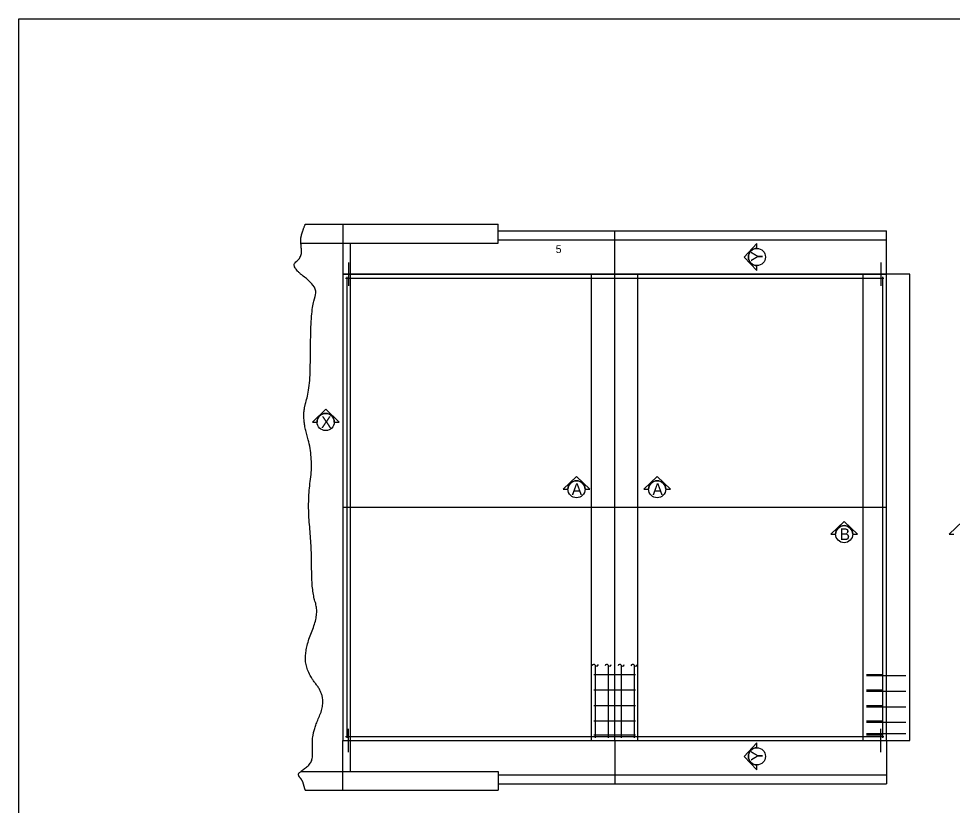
# Model space of a CAD drawing. Extents: x 1531 to 2925, y 1224 to 1658.
# Drawn here: x 2396.3 to 2456.4, y 1376.5 to 1427.1 of the extents above; entities that cross this region are included whole.
import ezdxf

# ---------------------------------------------------------------- set-up
doc = ezdxf.new("R2010")
doc.units = 0
for name, color, linetype in [('BD-EXIST-COSS', 7, 'Continuous'), ('BD-REMOVE', 7, 'Continuous'), ('D_BDR_TITLE_BLOCK_TEXT_TITLE', 7, 'Continuous'), ('R_Border_Scale', 7, 'Continuous'), ('R_Draft', 7, 'Continuous'), ('R_Survey Control', 7, 'Continuous'), ('R_Wall', 7, 'Continuous')]:
    doc.layers.add(name, color=color, linetype=linetype)

msp = doc.modelspace()

# ---------------------------------------------------------------- linework, layer by layer
at = {"layer": 'BD-EXIST-COSS'}
for p, q in [((2417.555, 1411.436), (2417.555, 1409.936)), ((2451.817, 1411.436), (2451.817, 1409.936)), ((2417.352, 1410.436), (2452.019, 1410.436)), ((2417.436, 1410.52), (2417.436, 1380.853)), ((2451.936, 1410.52), (2451.936, 1380.853)), ((2433.436, 1385.522), (2433.436, 1380.853)), ((2434.269, 1385.522), (2434.269, 1380.853)), ((2435.102, 1385.522), (2435.102, 1380.853)), ((2435.936, 1385.522), (2435.936, 1380.853)), ((2433.352, 1384.936), (2436.019, 1384.936)), ((2450.894, 1384.936), (2451.977, 1384.936)), ((2450.894, 1384.853), (2453.436, 1384.853)), ((2433.352, 1383.936), (2436.019, 1383.936)), ((2450.894, 1383.936), (2451.977, 1383.936)), ((2450.894, 1383.853), (2453.436, 1383.853)), ((2433.352, 1382.936), (2436.019, 1382.936)), ((2450.894, 1382.936), (2451.977, 1382.936)), ((2450.894, 1382.853), (2453.436, 1382.853)), ((2433.352, 1381.936), (2436.019, 1381.936)), ((2450.894, 1381.936), (2451.977, 1381.936)), ((2450.894, 1381.853), (2453.436, 1381.853)), ((2417.555, 1379.936), (2417.555, 1381.436)), ((2451.817, 1379.936), (2451.817, 1381.436)), ((2417.352, 1380.936), (2452.019, 1380.936)), ((2433.352, 1381.037), (2436.019, 1381.037)), ((2450.894, 1381.12), (2453.436, 1381.12)), ((2450.894, 1381.037), (2451.977, 1381.037))]:
    msp.add_line(p, q, dxfattribs=at)
for centre, start, end in [((2433.343, 1385.468), 30.26081, 174.78761), ((2433.528, 1385.576), 210.26064, 354.78668), ((2434.176, 1385.468), 30.26081, 174.78761), ((2434.362, 1385.576), 210.26064, 354.78668), ((2435.01, 1385.468), 30.26081, 174.78761), ((2435.195, 1385.576), 210.26064, 354.78668), ((2435.843, 1385.468), 30.26081, 174.78761), ((2436.028, 1385.576), 210.26064, 354.78668)]:
    msp.add_arc(centre, 0.107, start, end, dxfattribs=at)
at = {"layer": 'BD-REMOVE'}
for p, q in [((2414.767, 1413.895), (2417.186, 1413.895)), ((2417.186, 1413.895), (2417.186, 1412.686)), ((2417.186, 1413.895), (2427.186, 1413.895)), ((2427.186, 1412.686), (2427.186, 1413.895)), ((2427.186, 1413.478), (2452.186, 1413.478)), ((2434.686, 1410.686), (2434.686, 1413.478)), ((2434.686, 1410.686), (2434.686, 1413.478)), ((2452.186, 1410.686), (2452.186, 1413.478)), ((2414.493, 1412.686), (2417.186, 1412.686)), ((2417.186, 1412.686), (2427.186, 1412.686)), ((2417.186, 1412.686), (2417.186, 1410.686)), ((2417.686, 1378.686), (2417.686, 1412.686)), ((2427.186, 1412.895), (2452.186, 1412.895)), ((2417.186, 1410.686), (2452.186, 1410.686)), ((2417.186, 1378.686), (2417.186, 1380.686)), ((2417.186, 1380.686), (2452.186, 1380.686)), ((2434.686, 1380.686), (2434.686, 1377.895)), ((2452.186, 1380.686), (2452.186, 1377.895)), ((2414.493, 1378.686), (2417.186, 1378.686)), ((2417.186, 1377.478), (2417.186, 1378.686)), ((2417.186, 1378.686), (2427.186, 1378.686)), ((2427.186, 1378.686), (2427.186, 1377.478)), ((2427.186, 1378.478), (2452.186, 1378.478)), ((2427.186, 1377.895), (2452.186, 1377.895)), ((2414.767, 1377.478), (2417.186, 1377.478)), ((2417.186, 1377.478), (2427.186, 1377.478))]:
    msp.add_line(p, q, dxfattribs=at)
msp.add_open_spline([(2414.767, 1377.478), (2414.66, 1377.857), (2414.588, 1378.103), (2414.265, 1378.489), (2414.479, 1378.686), (2415.233, 1379.25), (2415.233, 1380.198), (2415.233, 1381.224), (2416.18, 1383.403), (2414.781, 1385.149), (2414.781, 1386.723), (2415.662, 1388.832), (2415.178, 1390.267), (2415.178, 1393.172), (2414.902, 1396.008), (2415.299, 1398.896), (2414.504, 1401.559), (2415.109, 1403.271), (2415.109, 1408.51), (2415.662, 1409.807), (2413.778, 1411.19), (2414.573, 1411.778), (2414.479, 1412.686), (2414.479, 1413.162), (2414.767, 1413.895)], degree=2, dxfattribs=at)
at = {"layer": 'D_BDR_TITLE_BLOCK_TEXT_TITLE'}
for p, q in [((2433.186, 1380.686), (2433.186, 1410.686)), ((2436.186, 1380.686), (2436.186, 1410.686)), ((2450.686, 1380.686), (2450.686, 1410.686))]:
    msp.add_line(p, q, dxfattribs=at)
at = {"layer": 'R_Draft'}
for p, q in [((2417.186, 1410.686), (2417.186, 1380.686)), ((2453.686, 1410.686), (2417.186, 1410.686)), ((2434.686, 1380.686), (2434.686, 1410.686)), ((2452.186, 1380.686), (2452.186, 1410.686)), ((2453.686, 1380.686), (2453.686, 1410.686)), ((2417.186, 1395.686), (2452.186, 1395.686)), ((2417.186, 1380.686), (2453.686, 1380.686))]:
    msp.add_line(p, q, dxfattribs=at)
at = {"layer": 'R_Survey Control'}
for points in [[(2443.844, 1412.342), (2443.844, 1412.649), (2443.017, 1411.789), (2443.844, 1410.93), (2443.844, 1411.237)], [(2416.635, 1401.173), (2416.942, 1401.173), (2416.082, 1402), (2415.223, 1401.173), (2415.53, 1401.173)], [(2432.78, 1396.846), (2433.087, 1396.846), (2432.228, 1397.672), (2431.368, 1396.846), (2431.675, 1396.846)], [(2437.978, 1396.846), (2438.285, 1396.846), (2437.425, 1397.672), (2436.566, 1396.846), (2436.873, 1396.846)], [(2450.015, 1393.954), (2450.322, 1393.954), (2449.462, 1394.78), (2448.603, 1393.954), (2448.91, 1393.954)], [(2457.633, 1393.954), (2457.94, 1393.954), (2457.08, 1394.78), (2456.221, 1393.954), (2456.528, 1393.954)], [(2443.844, 1380.211), (2443.844, 1380.519), (2443.017, 1379.659), (2443.844, 1378.799), (2443.844, 1379.107)]]:
    msp.add_lwpolyline(points, dxfattribs=at)
for centre in [(2443.844, 1411.787), (2416.082, 1401.173), (2432.228, 1396.846), (2437.423, 1396.846), (2449.462, 1393.954), (2443.844, 1379.659)]:
    msp.add_circle(centre, 0.552, dxfattribs=at)
for centre, start, end in [((2443.844, 1411.789), 90, 270), ((2416.082, 1401.173), 360, 180), ((2432.228, 1396.846), 360, 180), ((2437.425, 1396.846), 360, 180), ((2449.462, 1393.954), 360, 180), ((2443.844, 1379.659), 90, 270)]:
    msp.add_arc(centre, 0.552, start, end, dxfattribs=at)
at = {"layer": 'R_Wall'}
msp.add_lwpolyline([(2396.317, 1427.125), (2541.534, 1427.125), (2541.534, 1330.23), (2396.317, 1330.23)], close=True, dxfattribs=at)

# ---------------------------------------------------------------- texts
at = {"layer": 'R_Border_Scale'}
msp.add_text('5', height=0.5, dxfattribs=at).set_placement((2430.891, 1412.049))
at = {"layer": 'R_Survey Control'}
for p in [(2444.219, 1411.491), (2444.219, 1379.358)]:
    msp.add_text('Y', height=0.75, rotation=90, dxfattribs=at).set_placement(p)
for s, p in [('X', (2415.785, 1400.798)), ('A', (2431.916, 1396.471)), ('A', (2437.116, 1396.471)), ('B', (2449.17, 1393.579))]:
    msp.add_text(s, height=0.75, dxfattribs=at).set_placement(p)

doc.saveas('drawing.dxf')
